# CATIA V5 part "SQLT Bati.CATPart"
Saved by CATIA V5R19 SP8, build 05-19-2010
Part number: SQLT Bati
Publications: "Droite.1", "Droite.2", "Droite.3", "Plan.1", "Plan.2", "Plan.3", "Plan.4", "Plan.5"
Bounding box of the stored display mesh (mm): x -1000 to 1000, y -1250 to 2700, z 0 to 3600
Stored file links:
  C:\Users\ThinkMotion\Desktop\EU_thinkMotion\iao\IAO_MMS_Groupe3\fovide\fovide\SQLT Bati.CATPart
  C:\Users\ThinkMotion\Desktop\EU_thinkMotion\iao\IAO_MMS_Groupe3\fovide\fovide\fovide.CATProduct
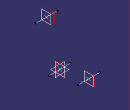
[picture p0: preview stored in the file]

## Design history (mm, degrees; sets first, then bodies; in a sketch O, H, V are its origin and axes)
External parameters (linked from other documents)
  `External.Diamètre bielle` = 150 mm
  `External.Rayon bielle` = 75 mm
Set1
  Point1 "Point.D": linked copy from another document
  Point2 "Point.A": linked copy from another document
  Point3 "Point.E": linked copy from another document
Set2 "set bati"
  Line1: type Normal, RefPoint Point1, RefSkin yz-plane, Start -1000, End 1000
  Line2: type Normal, RefPoint Point2, RefSkin yz-plane, Start -1000, End 1000
  Line3: type Normal, RefPoint Point3, RefSkin yz-plane, Start -1000, End 1000
  Plane1: type OffsetPt, RefPlane yz-plane, RefPoint Point2
  Plane2: type OffsetPt, RefPlane yz-plane, RefPoint Point3
  Plane3: type Offset, RefPlane Plane2, Offset 300 {= `External.Diamètre bielle` *2}, reversed
  Plane4: type Offset, RefPlane Plane1, Offset 75 {= `External.Rayon bielle`}, reversed
  Plane5: type Offset, RefPlane yz-plane, Offset 75 {= `External.Rayon bielle`}, reversed
Body1 (main body)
